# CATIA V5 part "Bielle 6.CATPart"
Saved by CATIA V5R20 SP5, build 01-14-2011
Part number: Bielle 6
Bounding box of the stored display mesh (mm): x -280 to -240, y -210 to 110, z 15 to 25
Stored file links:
  U:\CFAO\Thinkmotion\Bielle 6.CATPart
  U:\CFAO\Thinkmotion\Bras Articule.CATProduct
  U:\CFAO\Thinkmotion\Squelette Bielle 6.CATPart
  U:\CFAO\Thinkmotion\Bielle 5.CATPart
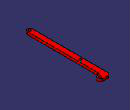
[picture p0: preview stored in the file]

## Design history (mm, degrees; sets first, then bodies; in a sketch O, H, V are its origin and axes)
Set1
  Plane1: linked copy from another document
  Line1: linked copy from another document
  Line2: linked copy from another document
  Point1 to Point3: linked copy from another document
Body1 (main body)
  Sketch1 on Plane1, origin (0, 0, 20), H (1, 0, 0), V (0, 1, 0)
    line L1 (-250, 110) -> (-280, 110)
    line L2 (-280, 110) -> (-280, -200)
    arc A1 centre (-270, -200) radius 10 from (-280, -200) to (-260, -200) ccw
    line L3 (-260, -200) -> (-260, 90)
    line L4 (-260, 90) -> (-250, 90)
    arc A2 centre (-250, 100) radius 10 from (-250, 90) to (-250, 110) ccw
    reference projected line E1 (-270, 100) -> (-270, 0) from Line1
    reference projected line E2 (-270, 100) -> (-270, 0) from Line1
    reference projected line E3 (-250, 100) -> (-270, 100) from Line2
    reference projected line E4 (-250, 100) -> (-270, 100) from Line2
    reference projected line E5 (-270, 100) -> (-270, 0) from Line1
    reference projected point E6 (-270, -200) from Point1
    reference projected point E7 (-250, 100) from Point2
    circle A3 centre (-250, 100) radius 5
    circle A4 centre (-270, 0) radius 5
    point P9 (-270, 0)
    reference projected point E8 (-270, 0) from Point3
    circle A5 centre (-270, -200) radius 5
    reference projected point E9 (-270, -200) from Point1
    distance L1 E4 = 10
    distance L2 E5 = 10
    radius A3 = 5
    radius A4 = 5
    radius A5 = 5
    horizontal: L1 H, L4 H
    vertical: L2 V
    tangency: A1 L2, L3 A1, A2 L1, A2 L4
    symmetry: L2 L3 E1, L4 L1 E3
    parallelism: L2 L3, L3 E2
    concentricity: E6 A1, A2 E7, A3 A2, A4 E8, A5 E9
    coincidence: P9 H
  Pad1: profile Sketch1, direction (0, 0, 1), length 5, mirrored extent
  Fillet1: radius 10, on edge [face of Pad1 from Sketch1.L2 | face of Pad1 from Sketch1.L1]; edge [face of Pad1 from Sketch1.L4 | face of Pad1 from Sketch1.L3]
